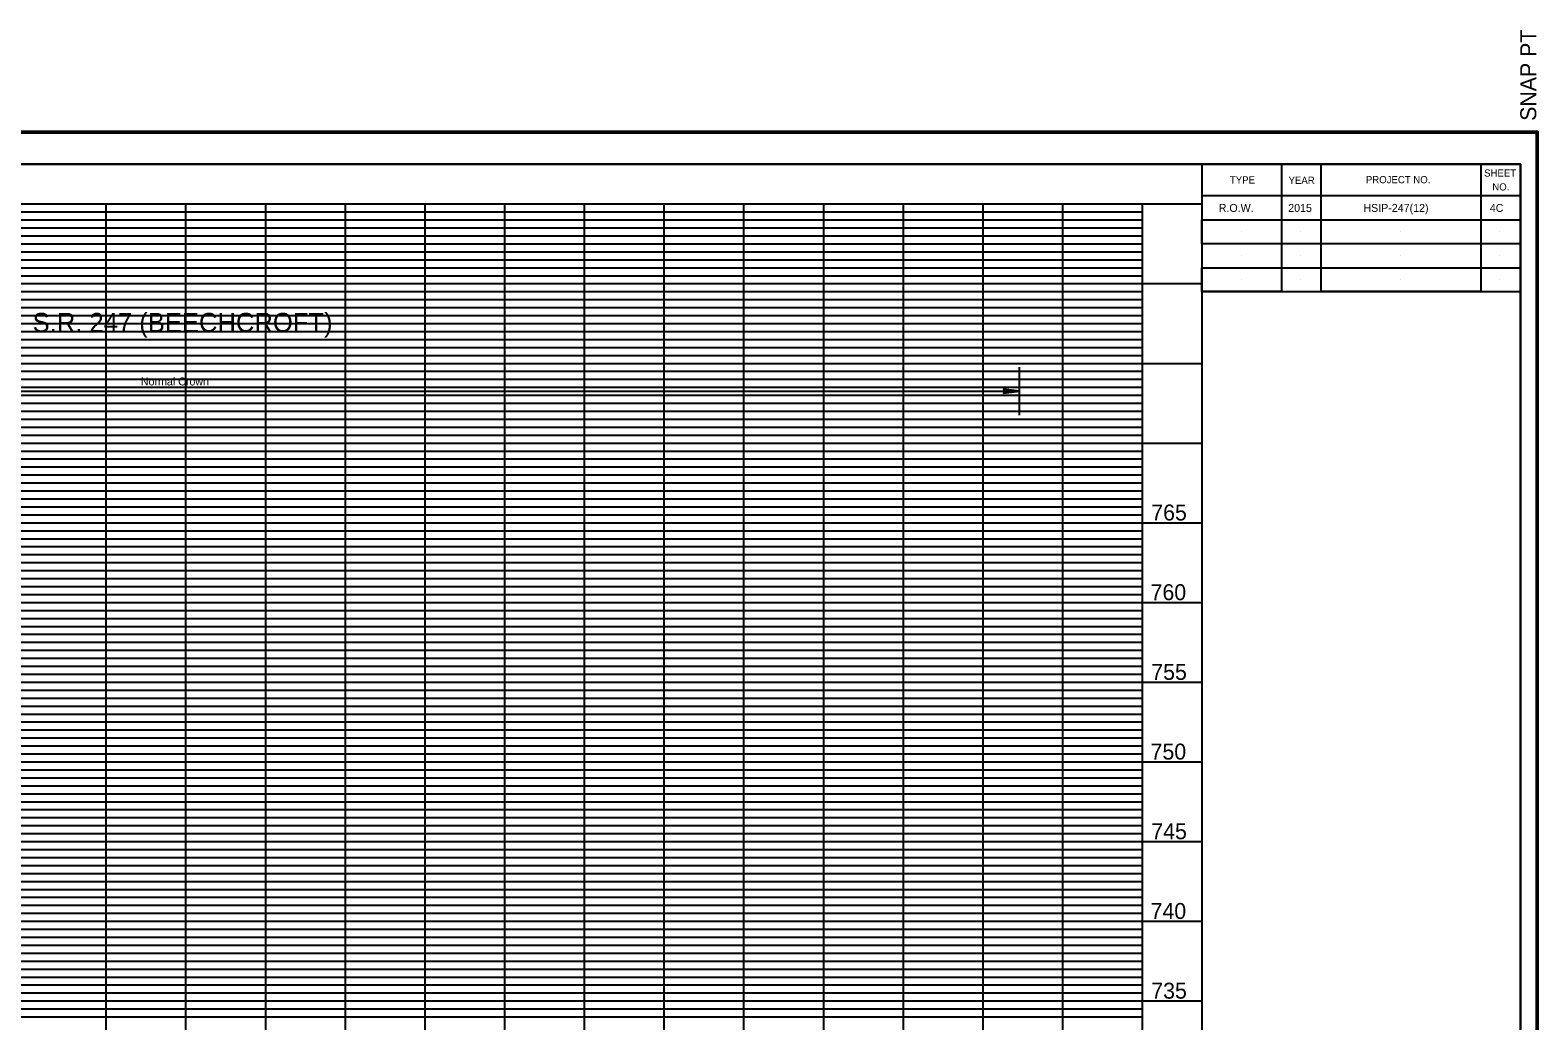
# Model space of a CAD drawing. Extents: x -273 to 1681765, y -325 to 521384.
# Drawn here: x 1680819 to 1681765, y 520762 to 521384 of the extents above; entities that cross this region are included whole.
import ezdxf

# ---------------------------------------------------------------- set-up
doc = ezdxf.new("R2010")
doc.units = 0
for name, color, linetype in [('DESIGN - PROFILE - Proposed Text', 7, 'Continuous'), ('DESIGN - SCRATCH - User 1', 7, 'Continuous'), ('DESIGN - SHEET - Corner Text', 7, 'Continuous'), ('DESIGN - SHEET - Light Grid', 7, 'Continuous'), ('DESIGN - SHEET - Linework', 7, 'Continuous'), ('DESIGN - SHEET - Plot Shape', 7, 'Continuous')]:
    doc.layers.add(name, color=color, linetype=linetype)

msp = doc.modelspace()

# ---------------------------------------------------------------- linework, layer by layer
at = {"layer": 'DESIGN - PROFILE - Proposed Text'}
for p, q in [((1681439.9, 521142.33), (1681439.9, 521172.33)), ((1680389.9, 521157.33), (1681439.9, 521157.33))]:
    msp.add_line(p, q, dxfattribs=at)
msp.add_lwpolyline([(1681439.9, 521157.33), (1681429.85, 521158.58), (1681431.15, 521157.33), (1681429.85, 521156.03)], close=True, dxfattribs=at)
msp.add_lwpolyline([(1681439.9, 521157.33), (1681429.85, 521158.58), (1681431.15, 521157.33), (1681429.85, 521156.03), (1681439.9, 521157.33)], dxfattribs=at)
at = {"layer": 'DESIGN - SCRATCH - User 1'}
for p, q in [((1681579.23, 521272.26), (1681579.23, 521272.26)), ((1681616.23, 521272.26), (1681616.23, 521272.26)), ((1681678.73, 521272.26), (1681678.73, 521272.26)), ((1681741.23, 521272.26), (1681741.23, 521272.26)), ((1681579.23, 521257.26), (1681579.23, 521257.26)), ((1681616.23, 521257.26), (1681616.23, 521257.26)), ((1681678.73, 521257.26), (1681678.73, 521257.26)), ((1681741.23, 521257.26), (1681741.23, 521257.26)), ((1681579.23, 521242.26), (1681579.23, 521242.26)), ((1681616.23, 521242.26), (1681616.23, 521242.26)), ((1681678.73, 521242.26), (1681678.73, 521242.26)), ((1681741.23, 521242.26), (1681741.23, 521242.26)), ((1681579.23, 521227.26), (1681579.23, 521227.26)), ((1681616.23, 521227.26), (1681616.23, 521227.26)), ((1681678.73, 521227.26), (1681678.73, 521227.26)), ((1681741.23, 521227.26), (1681741.23, 521227.26))]:
    msp.add_line(p, q, dxfattribs=at)
at = {"layer": 'DESIGN - SHEET - Light Grid'}
for p, q in [((1680517.13, 521269.76), (1680867.13, 521269.76)), ((1680867.13, 521269.76), (1681217.13, 521269.76)), ((1681217.13, 521269.76), (1681517.13, 521269.76)), ((1680517.13, 521264.76), (1680867.13, 521264.76)), ((1680517.13, 521259.76), (1680867.13, 521259.76)), ((1680867.13, 521264.76), (1681217.13, 521264.76)), ((1680867.13, 521259.76), (1681217.13, 521259.76)), ((1681217.13, 521264.76), (1681517.13, 521264.76)), ((1681217.13, 521259.76), (1681517.13, 521259.76)), ((1680517.13, 521254.76), (1680867.13, 521254.76)), ((1680517.13, 521249.76), (1680867.13, 521249.76)), ((1680867.13, 521254.76), (1681217.13, 521254.76)), ((1680867.13, 521249.76), (1681217.13, 521249.76)), ((1681217.13, 521254.76), (1681517.13, 521254.76)), ((1681217.13, 521249.76), (1681517.13, 521249.76)), ((1680517.13, 521244.76), (1680867.13, 521244.76)), ((1680517.13, 521239.76), (1680867.13, 521239.76)), ((1680867.13, 521244.76), (1681217.13, 521244.76)), ((1680867.13, 521239.76), (1681217.13, 521239.76)), ((1681217.13, 521244.76), (1681517.13, 521244.76)), ((1681217.13, 521239.76), (1681517.13, 521239.76)), ((1680517.13, 521234.76), (1680867.13, 521234.76)), ((1680517.13, 521229.76), (1680867.13, 521229.76)), ((1680867.13, 521234.76), (1681217.13, 521234.76)), ((1680867.13, 521229.76), (1681217.13, 521229.76)), ((1681217.13, 521234.76), (1681517.13, 521234.76)), ((1681217.13, 521229.76), (1681517.13, 521229.76)), ((1680517.13, 521219.76), (1680867.13, 521219.76)), ((1680867.13, 521219.76), (1681217.13, 521219.76)), ((1681217.13, 521219.76), (1681517.13, 521219.76)), ((1680517.13, 521214.76), (1680867.13, 521214.76)), ((1680867.13, 521214.76), (1681217.13, 521214.76)), ((1681217.13, 521214.76), (1681517.13, 521214.76)), ((1680517.13, 521209.76), (1680867.13, 521209.76)), ((1680517.13, 521204.76), (1680867.13, 521204.76)), ((1680867.13, 521209.76), (1681217.13, 521209.76)), ((1680867.13, 521204.76), (1681217.13, 521204.76)), ((1681217.13, 521209.76), (1681517.13, 521209.76)), ((1681217.13, 521204.76), (1681517.13, 521204.76)), ((1680517.13, 521199.76), (1680867.13, 521199.76)), ((1680517.13, 521194.76), (1680867.13, 521194.76)), ((1680867.13, 521199.76), (1681217.13, 521199.76)), ((1680867.13, 521194.76), (1681217.13, 521194.76)), ((1681217.13, 521199.76), (1681517.13, 521199.76)), ((1681217.13, 521194.76), (1681517.13, 521194.76)), ((1680517.13, 521189.76), (1680867.13, 521189.76)), ((1680517.13, 521184.76), (1680867.13, 521184.76)), ((1680867.13, 521189.76), (1681217.13, 521189.76)), ((1680867.13, 521184.76), (1681217.13, 521184.76)), ((1681217.13, 521189.76), (1681517.13, 521189.76)), ((1681217.13, 521184.76), (1681517.13, 521184.76)), ((1680517.13, 521179.76), (1680867.13, 521179.76)), ((1680867.13, 521179.76), (1681217.13, 521179.76)), ((1681217.13, 521179.76), (1681517.13, 521179.76)), ((1680517.13, 521169.76), (1680867.13, 521169.76)), ((1680517.13, 521164.76), (1680867.13, 521164.76)), ((1680867.13, 521169.76), (1681217.13, 521169.76)), ((1680867.13, 521164.76), (1681217.13, 521164.76)), ((1681217.13, 521169.76), (1681517.13, 521169.76)), ((1681217.13, 521164.76), (1681517.13, 521164.76)), ((1680517.13, 521159.76), (1680867.13, 521159.76)), ((1680517.13, 521154.76), (1680867.13, 521154.76)), ((1680867.13, 521159.76), (1681217.13, 521159.76)), ((1680867.13, 521154.76), (1681217.13, 521154.76)), ((1681217.13, 521159.76), (1681517.13, 521159.76)), ((1681217.13, 521154.76), (1681517.13, 521154.76)), ((1680517.13, 521149.76), (1680867.13, 521149.76)), ((1680517.13, 521144.76), (1680867.13, 521144.76)), ((1680867.13, 521149.76), (1681217.13, 521149.76)), ((1680867.13, 521144.76), (1681217.13, 521144.76)), ((1681217.13, 521149.76), (1681517.13, 521149.76)), ((1681217.13, 521144.76), (1681517.13, 521144.76)), ((1680517.13, 521139.76), (1680867.13, 521139.76)), ((1680517.13, 521134.76), (1680867.13, 521134.76)), ((1680867.13, 521139.76), (1681217.13, 521139.76)), ((1680867.13, 521134.76), (1681217.13, 521134.76)), ((1681217.13, 521139.76), (1681517.13, 521139.76)), ((1681217.13, 521134.76), (1681517.13, 521134.76)), ((1680517.13, 521129.76), (1680867.13, 521129.76)), ((1680867.13, 521129.76), (1681217.13, 521129.76)), ((1681217.13, 521129.76), (1681517.13, 521129.76)), ((1680517.13, 521119.76), (1680867.13, 521119.76)), ((1680867.13, 521119.76), (1681217.13, 521119.76)), ((1681217.13, 521119.76), (1681517.13, 521119.76)), ((1680517.13, 521114.76), (1680867.13, 521114.76)), ((1680517.13, 521109.76), (1680867.13, 521109.76)), ((1680867.13, 521114.76), (1681217.13, 521114.76)), ((1680867.13, 521109.76), (1681217.13, 521109.76)), ((1681217.13, 521114.76), (1681517.13, 521114.76)), ((1681217.13, 521109.76), (1681517.13, 521109.76)), ((1680517.13, 521104.76), (1680867.13, 521104.76)), ((1680517.13, 521099.76), (1680867.13, 521099.76)), ((1680867.13, 521104.76), (1681217.13, 521104.76)), ((1680867.13, 521099.76), (1681217.13, 521099.76)), ((1681217.13, 521104.76), (1681517.13, 521104.76)), ((1681217.13, 521099.76), (1681517.13, 521099.76)), ((1680517.13, 521094.76), (1680867.13, 521094.76)), ((1680517.13, 521089.76), (1680867.13, 521089.76)), ((1680867.13, 521094.76), (1681217.13, 521094.76)), ((1680867.13, 521089.76), (1681217.13, 521089.76)), ((1681217.13, 521094.76), (1681517.13, 521094.76)), ((1681217.13, 521089.76), (1681517.13, 521089.76)), ((1680517.13, 521084.76), (1680867.13, 521084.76)), ((1680517.13, 521079.76), (1680867.13, 521079.76)), ((1680867.13, 521084.76), (1681217.13, 521084.76)), ((1680867.13, 521079.76), (1681217.13, 521079.76)), ((1681217.13, 521084.76), (1681517.13, 521084.76)), ((1681217.13, 521079.76), (1681517.13, 521079.76)), ((1680517.13, 521069.76), (1680867.13, 521069.76)), ((1680867.13, 521069.76), (1681217.13, 521069.76)), ((1681217.13, 521069.76), (1681517.13, 521069.76)), ((1680517.13, 521064.76), (1680867.13, 521064.76)), ((1680517.13, 521059.76), (1680867.13, 521059.76)), ((1680867.13, 521064.76), (1681217.13, 521064.76)), ((1680867.13, 521059.76), (1681217.13, 521059.76)), ((1681217.13, 521064.76), (1681517.13, 521064.76)), ((1681217.13, 521059.76), (1681517.13, 521059.76)), ((1680517.13, 521054.76), (1680867.13, 521054.76)), ((1680517.13, 521049.76), (1680867.13, 521049.76)), ((1680867.13, 521054.76), (1681217.13, 521054.76)), ((1680867.13, 521049.76), (1681217.13, 521049.76)), ((1681217.13, 521054.76), (1681517.13, 521054.76)), ((1681217.13, 521049.76), (1681517.13, 521049.76)), ((1680517.13, 521044.76), (1680867.13, 521044.76)), ((1680867.13, 521044.76), (1681217.13, 521044.76)), ((1681217.13, 521044.76), (1681517.13, 521044.76)), ((1680517.13, 521039.76), (1680867.13, 521039.76)), ((1680517.13, 521034.76), (1680867.13, 521034.76)), ((1680867.13, 521039.76), (1681217.13, 521039.76)), ((1680867.13, 521034.76), (1681217.13, 521034.76)), ((1681217.13, 521039.76), (1681517.13, 521039.76)), ((1681217.13, 521034.76), (1681517.13, 521034.76)), ((1680517.13, 521029.76), (1680867.13, 521029.76)), ((1680867.13, 521029.76), (1681217.13, 521029.76)), ((1681217.13, 521029.76), (1681517.13, 521029.76)), ((1680517.13, 521019.76), (1680867.13, 521019.76)), ((1680517.13, 521014.76), (1680867.13, 521014.76)), ((1680867.13, 521019.76), (1681217.13, 521019.76)), ((1680867.13, 521014.76), (1681217.13, 521014.76)), ((1681217.13, 521019.76), (1681517.13, 521019.76)), ((1681217.13, 521014.76), (1681517.13, 521014.76)), ((1680517.13, 521009.76), (1680867.13, 521009.76)), ((1680517.13, 521004.76), (1680867.13, 521004.76)), ((1680867.13, 521009.76), (1681217.13, 521009.76)), ((1680867.13, 521004.76), (1681217.13, 521004.76)), ((1681217.13, 521009.76), (1681517.13, 521009.76)), ((1681217.13, 521004.76), (1681517.13, 521004.76)), ((1680517.13, 520999.76), (1680867.13, 520999.76)), ((1680517.13, 520994.76), (1680867.13, 520994.76)), ((1680867.13, 520999.76), (1681217.13, 520999.76)), ((1680867.13, 520994.76), (1681217.13, 520994.76)), ((1681217.13, 520999.76), (1681517.13, 520999.76)), ((1681217.13, 520994.76), (1681517.13, 520994.76)), ((1680517.13, 520989.76), (1680867.13, 520989.76)), ((1680517.13, 520984.76), (1680867.13, 520984.76)), ((1680867.13, 520989.76), (1681217.13, 520989.76)), ((1680867.13, 520984.76), (1681217.13, 520984.76)), ((1681217.13, 520989.76), (1681517.13, 520989.76)), ((1681217.13, 520984.76), (1681517.13, 520984.76)), ((1680517.13, 520979.76), (1680867.13, 520979.76)), ((1680867.13, 520979.76), (1681217.13, 520979.76)), ((1681217.13, 520979.76), (1681517.13, 520979.76)), ((1680517.13, 520969.76), (1680867.13, 520969.76)), ((1680517.13, 520964.76), (1680867.13, 520964.76)), ((1680867.13, 520969.76), (1681217.13, 520969.76)), ((1680867.13, 520964.76), (1681217.13, 520964.76)), ((1681217.13, 520969.76), (1681517.13, 520969.76)), ((1681217.13, 520964.76), (1681517.13, 520964.76)), ((1680517.13, 520959.76), (1680867.13, 520959.76)), ((1680867.13, 520959.76), (1681217.13, 520959.76)), ((1681217.13, 520959.76), (1681517.13, 520959.76)), ((1680517.13, 520954.76), (1680867.13, 520954.76)), ((1680517.13, 520949.76), (1680867.13, 520949.76)), ((1680867.13, 520954.76), (1681217.13, 520954.76)), ((1680867.13, 520949.76), (1681217.13, 520949.76)), ((1681217.13, 520954.76), (1681517.13, 520954.76)), ((1681217.13, 520949.76), (1681517.13, 520949.76)), ((1680517.13, 520944.76), (1680867.13, 520944.76)), ((1680517.13, 520939.76), (1680867.13, 520939.76)), ((1680867.13, 520944.76), (1681217.13, 520944.76)), ((1680867.13, 520939.76), (1681217.13, 520939.76)), ((1681217.13, 520944.76), (1681517.13, 520944.76)), ((1681217.13, 520939.76), (1681517.13, 520939.76)), ((1680517.13, 520934.76), (1680867.13, 520934.76)), ((1680517.13, 520929.76), (1680867.13, 520929.76)), ((1680867.13, 520934.76), (1681217.13, 520934.76)), ((1680867.13, 520929.76), (1681217.13, 520929.76)), ((1681217.13, 520934.76), (1681517.13, 520934.76)), ((1681217.13, 520929.76), (1681517.13, 520929.76)), ((1680517.13, 520919.76), (1680867.13, 520919.76)), ((1680867.13, 520919.76), (1681217.13, 520919.76)), ((1681217.13, 520919.76), (1681517.13, 520919.76)), ((1680517.13, 520914.76), (1680867.13, 520914.76)), ((1680517.13, 520909.76), (1680867.13, 520909.76)), ((1680867.13, 520914.76), (1681217.13, 520914.76)), ((1680867.13, 520909.76), (1681217.13, 520909.76)), ((1681217.13, 520914.76), (1681517.13, 520914.76)), ((1681217.13, 520909.76), (1681517.13, 520909.76)), ((1680517.13, 520904.76), (1680867.13, 520904.76)), ((1680517.13, 520899.76), (1680867.13, 520899.76)), ((1680867.13, 520904.76), (1681217.13, 520904.76)), ((1680867.13, 520899.76), (1681217.13, 520899.76)), ((1681217.13, 520904.76), (1681517.13, 520904.76)), ((1681217.13, 520899.76), (1681517.13, 520899.76)), ((1680517.13, 520894.76), (1680867.13, 520894.76)), ((1680517.13, 520889.76), (1680867.13, 520889.76)), ((1680867.13, 520894.76), (1681217.13, 520894.76)), ((1680867.13, 520889.76), (1681217.13, 520889.76)), ((1681217.13, 520894.76), (1681517.13, 520894.76)), ((1681217.13, 520889.76), (1681517.13, 520889.76)), ((1680517.13, 520884.76), (1680867.13, 520884.76)), ((1680517.13, 520879.76), (1680867.13, 520879.76)), ((1680867.13, 520884.76), (1681217.13, 520884.76)), ((1680867.13, 520879.76), (1681217.13, 520879.76)), ((1681217.13, 520884.76), (1681517.13, 520884.76)), ((1681217.13, 520879.76), (1681517.13, 520879.76)), ((1680517.13, 520869.76), (1680867.13, 520869.76)), ((1680867.13, 520869.76), (1681217.13, 520869.76)), ((1681217.13, 520869.76), (1681517.13, 520869.76)), ((1680517.13, 520864.76), (1680867.13, 520864.76)), ((1680867.13, 520864.76), (1681217.13, 520864.76)), ((1681217.13, 520864.76), (1681517.13, 520864.76)), ((1680517.13, 520859.76), (1680867.13, 520859.76)), ((1680517.13, 520854.76), (1680867.13, 520854.76)), ((1680867.13, 520859.76), (1681217.13, 520859.76)), ((1680867.13, 520854.76), (1681217.13, 520854.76)), ((1681217.13, 520859.76), (1681517.13, 520859.76)), ((1681217.13, 520854.76), (1681517.13, 520854.76)), ((1680517.13, 520849.76), (1680867.13, 520849.76)), ((1680517.13, 520844.76), (1680867.13, 520844.76)), ((1680867.13, 520849.76), (1681217.13, 520849.76)), ((1680867.13, 520844.76), (1681217.13, 520844.76)), ((1681217.13, 520849.76), (1681517.13, 520849.76)), ((1681217.13, 520844.76), (1681517.13, 520844.76)), ((1680517.13, 520839.76), (1680867.13, 520839.76)), ((1680517.13, 520834.76), (1680867.13, 520834.76)), ((1680867.13, 520839.76), (1681217.13, 520839.76)), ((1680867.13, 520834.76), (1681217.13, 520834.76)), ((1681217.13, 520839.76), (1681517.13, 520839.76)), ((1681217.13, 520834.76), (1681517.13, 520834.76)), ((1680517.13, 520829.76), (1680867.13, 520829.76)), ((1680867.13, 520829.76), (1681217.13, 520829.76)), ((1681217.13, 520829.76), (1681517.13, 520829.76)), ((1680517.13, 520819.76), (1680867.13, 520819.76)), ((1680517.13, 520814.76), (1680867.13, 520814.76)), ((1680867.13, 520819.76), (1681217.13, 520819.76)), ((1680867.13, 520814.76), (1681217.13, 520814.76)), ((1681217.13, 520819.76), (1681517.13, 520819.76)), ((1681217.13, 520814.76), (1681517.13, 520814.76)), ((1680517.13, 520809.76), (1680867.13, 520809.76)), ((1680517.13, 520804.76), (1680867.13, 520804.76)), ((1680867.13, 520809.76), (1681217.13, 520809.76)), ((1680867.13, 520804.76), (1681217.13, 520804.76)), ((1681217.13, 520809.76), (1681517.13, 520809.76)), ((1681217.13, 520804.76), (1681517.13, 520804.76)), ((1680517.13, 520799.76), (1680867.13, 520799.76)), ((1680517.13, 520794.76), (1680867.13, 520794.76)), ((1680867.13, 520799.76), (1681217.13, 520799.76)), ((1680867.13, 520794.76), (1681217.13, 520794.76)), ((1681217.13, 520799.76), (1681517.13, 520799.76)), ((1681217.13, 520794.76), (1681517.13, 520794.76)), ((1680517.13, 520789.76), (1680867.13, 520789.76)), ((1680517.13, 520784.76), (1680867.13, 520784.76)), ((1680867.13, 520789.76), (1681217.13, 520789.76)), ((1680867.13, 520784.76), (1681217.13, 520784.76)), ((1681217.13, 520789.76), (1681517.13, 520789.76)), ((1681217.13, 520784.76), (1681517.13, 520784.76)), ((1680517.13, 520779.76), (1680867.13, 520779.76)), ((1680867.13, 520779.76), (1681217.13, 520779.76)), ((1681217.13, 520779.76), (1681517.13, 520779.76)), ((1680517.13, 520769.76), (1680867.13, 520769.76)), ((1680867.13, 520769.76), (1681217.13, 520769.76)), ((1681217.13, 520769.76), (1681517.13, 520769.76)), ((1680517.13, 520764.76), (1680867.13, 520764.76)), ((1680867.13, 520764.76), (1681217.13, 520764.76)), ((1681217.13, 520764.76), (1681517.13, 520764.76))]:
    msp.add_line(p, q, dxfattribs=at)
at = {"layer": 'DESIGN - SHEET - Linework'}
for p, q in [((1680063.08, 521320.46), (1681765.08, 521320.46)), ((1681765.08, 521320.46), (1681765.08, 520229.06)), ((1680182.13, 521274.76), (1681554.23, 521274.76)), ((1680867.13, 520274.76), (1680867.13, 521274.76)), ((1680917.13, 520274.76), (1680917.13, 521274.76)), ((1680967.13, 520274.76), (1680967.13, 521274.76)), ((1681017.13, 520274.76), (1681017.13, 521274.76)), ((1681067.13, 520274.76), (1681067.13, 521274.76)), ((1681117.13, 520274.76), (1681117.13, 521274.76)), ((1681167.13, 520274.76), (1681167.13, 521274.76)), ((1681217.13, 520274.76), (1681217.13, 521274.76)), ((1681267.13, 520274.76), (1681267.13, 521274.76)), ((1681317.13, 520274.76), (1681317.13, 521274.76)), ((1681367.13, 520274.76), (1681367.13, 521274.76)), ((1681417.13, 520274.76), (1681417.13, 521274.76)), ((1681467.13, 520274.76), (1681467.13, 521274.76)), ((1681517.13, 520274.76), (1681517.13, 521274.76)), ((1680180.03, 521224.76), (1681554.23, 521224.76)), ((1680180.03, 521174.76), (1681554.23, 521174.76)), ((1680180.03, 521124.76), (1681554.23, 521124.76)), ((1680180.03, 521074.76), (1681554.23, 521074.76)), ((1680180.03, 521024.76), (1681554.23, 521024.76)), ((1680180.03, 520974.76), (1681554.23, 520974.76)), ((1680180.03, 520924.76), (1681554.23, 520924.76)), ((1680180.03, 520874.76), (1681554.23, 520874.76)), ((1680180.03, 520824.76), (1681554.23, 520824.76)), ((1680180.03, 520774.76), (1681554.23, 520774.76))]:
    msp.add_line(p, q, dxfattribs=at)
for points in [[(1680180.03, 521299.76), (1680180.03, 520249.76), (1681754.23, 520249.76), (1681754.23, 521299.76), (1680180.03, 521299.76)], [(1681554.23, 521299.76), (1681554.23, 521219.76), (1681754.23, 521219.76), (1681754.23, 521299.76), (1681729.23, 521299.76), (1681729.23, 521219.76), (1681629.23, 521219.76), (1681629.23, 521299.76), (1681604.23, 521299.76), (1681604.23, 521219.76), (1681554.23, 521219.76), (1681554.23, 521234.76), (1681754.23, 521234.76), (1681754.23, 521249.76), (1681554.23, 521249.76), (1681554.23, 521264.76), (1681754.23, 521264.76), (1681754.23, 521279.76), (1681554.23, 521279.76)], [(1680180.03, 520274.76), (1680180.03, 521274.76), (1681554.23, 521274.76), (1681554.23, 520274.76), (1680182.13, 520274.76)]]:
    msp.add_lwpolyline(points, dxfattribs=at)
at = {"layer": 'DESIGN - SHEET - Plot Shape'}
for points in [[(1680064.08, 521319.46), (1681764.08, 521319.46), (1681764.08, 520230.06), (1680064.08, 520230.06)], [(1680094.98, 521299.76), (1681754.23, 521299.76), (1681754.23, 520249.76), (1680094.98, 520249.76)]]:
    msp.add_lwpolyline(points, close=True, dxfattribs=at)

# ---------------------------------------------------------------- texts
at = {"layer": 'DESIGN - PROFILE - Proposed Text'}
for s, height, p in [('S.R. 247 (BEECHCROFT)', 12, (1680820.95, 521194.43)), ('Normal Crown', 5, (1680888.85, 521160.9))]:
    msp.add_text(s, height=height, dxfattribs=at).set_placement(p)
at = {"layer": 'DESIGN - SHEET - Corner Text'}
msp.add_text('  SNAP PT', height=10, rotation=90, dxfattribs=at).set_placement((1681764.08, 521319.46))
for s, height, p in [('SHEET', 4.5, (1681731.38, 521291.91)), ('TYPE', 4.5, (1681571.93, 521287.56)), ('YEAR', 4.5, (1681608.73, 521287.36)), ('PROJECT NO.', 4.5, (1681657.23, 521287.76)), ('NO.', 4.5, (1681736.53, 521283.21)), ('  R.O.W.  ', 5, (1681561.21, 521269.76)), ('2015', 5, (1681608.51, 521269.76)), ('HSIP-247(12)', 5, (1681655.66, 521269.76)), (' 4C ', 5, (1681733.11, 521269.76)), ('765', 10, (1681522.62, 521076.18)), ('760', 10, (1681522.19, 521026.18)), ('755', 10, (1681522.62, 520976.18)), ('750', 10, (1681522.19, 520926.18)), ('745', 10, (1681522.62, 520876.18)), ('740', 10, (1681522.19, 520826.18)), ('735', 10, (1681522.62, 520776.18))]:
    msp.add_text(s, height=height, dxfattribs=at).set_placement(p)

doc.saveas('drawing.dxf')
